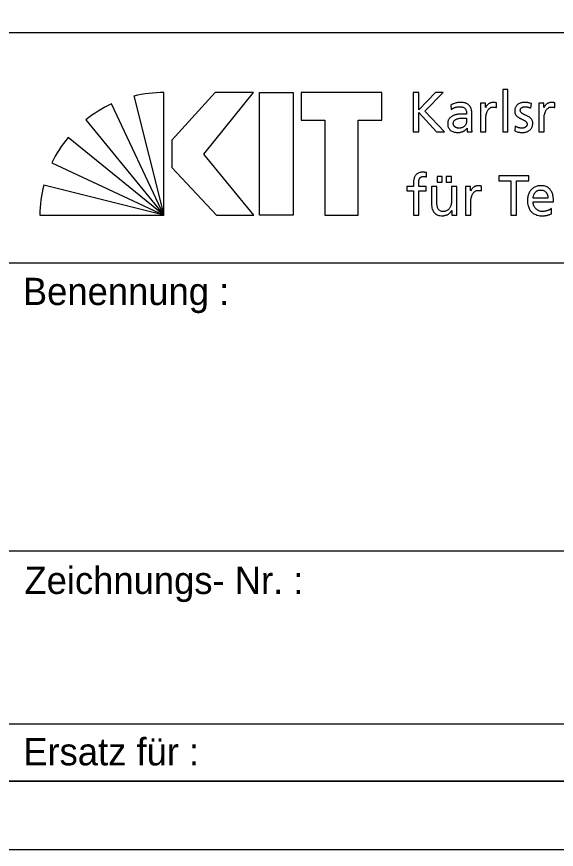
# Model space of a CAD drawing. Extents: x 0 to 1189, y 0 to 841.
# Drawn here: x 1100.7 to 1140.3, y 0 to 61.2 of the extents above; entities that cross this region are included whole.
import ezdxf

# ---------------------------------------------------------------- set-up
doc = ezdxf.new("R2010")
doc.units = 0
doc.layers.add('90_Plankopf', color=7, linetype='Continuous')

msp = doc.modelspace()

# ---------------------------------------------------------------- linework, layer by layer
at = {"layer": '90_Plankopf'}
for p, q in [((1006.12, 59.99), (1184, 59.99)), ((1006.12, 59.99), (1184, 59.99)), ((1109.275, 55.333), (1111.481, 46.586)), ((1111.481, 46.586), (1111.481, 55.584)), ((1129.81, 55.586), (1129.81, 52.706)), ((1111.481, 46.586), (1107.633, 54.752)), ((1132.579, 54.662), (1132.6, 54.332)), ((1135.926, 54.484), (1135.926, 54.831)), ((1138.457, 54.439), (1138.49, 54.778)), ((1140.211, 54.484), (1140.211, 54.831)), ((1134.118, 53.118), (1134.118, 53.989)), ((1105.744, 53.585), (1111.481, 46.586)), ((1133.73, 53.709), (1133.73, 53.523)), ((1129.81, 52.706), (1130.222, 52.706)), ((1131.506, 52.706), (1132.108, 52.706)), ((1137.297, 53.118), (1137.277, 52.772)), ((1111.481, 46.586), (1104.434, 52.286)), ((1103.24, 50.413), (1111.481, 46.586)), ((1130.773, 49.393), (1130.79, 49.706)), ((1111.481, 46.586), (1102.658, 48.788)), ((1134.827, 48.365), (1134.827, 48.712)), ((1139.706, 47.841), (1138.616, 47.841)), ((1138.616, 47.552), (1140.119, 47.552)), ((1102.364, 46.586), (1111.481, 46.586)), ((1139.958, 46.673), (1139.958, 47.061)), ((1100.001, 43.07), (1184, 43.07)), ((1100.001, 21.92), (1184, 21.92)), ((1100.001, 9.23), (1184, 9.23)), ((1184, 5), (1006.12, 5)), ((1017.8, 5), (1184, 5)), ((1017.8, 5), (1184, 5))]:
    msp.add_line(p, q, dxfattribs=at)
for points in [[(0, 0), (1189, 0), (1189, 841), (0, 841)], [(25, 5), (1184, 5), (1184, 836), (25, 836)], [(1118.066, 55.586), (1115.236, 55.586), (1112.073, 52.099), (1112.073, 50.092), (1115.338, 46.586), (1118.085, 46.586), (1114.422, 51.063)], [(1120.97, 55.586), (1120.97, 46.586), (1118.501, 46.586), (1118.501, 55.586)], [(1121.562, 55.586), (1121.562, 53.56), (1123.301, 53.56), (1123.301, 46.586), (1125.771, 46.586), (1125.771, 53.56), (1127.51, 53.56), (1127.51, 55.586)]]:
    msp.add_lwpolyline(points, close=True, dxfattribs=at)
for points in [[(1136.381, 52.706), (1136.768, 52.706), (1136.768, 55.801), (1136.381, 55.801), (1136.381, 52.706)], [(1132.108, 52.706), (1130.647, 54.224), (1132.001, 55.586), (1131.452, 55.586), (1130.222, 54.319), (1130.222, 55.586), (1129.81, 55.586)], [(1135.122, 54.484), (1135.113, 54.484), (1135.113, 54.81), (1134.75, 54.81), (1134.75, 52.706), (1135.138, 52.706), (1135.138, 53.663)], [(1139.407, 54.484), (1139.398, 54.484), (1139.398, 54.81), (1139.035, 54.81), (1139.035, 52.706), (1139.423, 52.706), (1139.423, 53.663)], [(1130.222, 52.706), (1130.222, 54.117), (1131.506, 52.706)], [(1133.763, 52.978), (1133.772, 52.978), (1133.772, 52.706), (1134.135, 52.706)], [(1131.554, 49.426), (1131.554, 49.013), (1131.942, 49.013), (1131.942, 49.426), (1131.554, 49.426)], [(1132.231, 49.426), (1132.231, 49.013), (1132.619, 49.013), (1132.619, 49.426), (1132.231, 49.426)], [(1136.99, 46.586), (1137.403, 46.586), (1137.403, 49.104), (1138.298, 49.104), (1138.298, 49.467), (1136.094, 49.467), (1136.094, 49.104), (1136.99, 49.104), (1136.99, 46.586)], [(1129.824, 48.885), (1129.824, 48.691), (1129.329, 48.691), (1129.329, 48.378), (1129.824, 48.378), (1129.824, 46.586), (1130.212, 46.586), (1130.212, 48.378), (1130.769, 48.378), (1130.769, 48.691), (1130.212, 48.691), (1130.212, 48.918)], [(1131.542, 47.602), (1131.542, 48.691), (1131.154, 48.691), (1131.154, 47.441)], [(1133.015, 46.586), (1133.015, 48.691), (1132.627, 48.691), (1132.627, 47.717)], [(1134.022, 48.365), (1134.014, 48.365), (1134.014, 48.691), (1133.651, 48.691), (1133.651, 46.586), (1134.039, 46.586), (1134.039, 47.544)], [(1132.631, 46.921), (1132.639, 46.921), (1132.639, 46.586), (1133.015, 46.586)]]:
    msp.add_lwpolyline(points, dxfattribs=at)
for centre, start, end in [((1111.449, 46.056), 89.80527, 103.18947), ((1111.662, 46.118), 115.01261, 128.3968), ((1111.816, 46.263), 140.78977, 154.17397), ((1111.891, 46.438), 165.72225, 179.10644)]:
    msp.add_arc(centre, 9.528, start, end, dxfattribs=at)
for points in [[(1134.118, 53.989), (1134.119, 54.18), (1134.091, 54.341), (1134.033, 54.47), (1133.975, 54.599), (1133.884, 54.696), (1133.759, 54.762), (1133.635, 54.827), (1133.472, 54.86), (1133.272, 54.86), (1133.138, 54.859), (1133.014, 54.841), (1132.898, 54.804), (1132.782, 54.768), (1132.676, 54.721), (1132.579, 54.662)], [(1132.6, 54.332), (1132.653, 54.376), (1132.713, 54.414), (1132.779, 54.446), (1132.846, 54.478), (1132.916, 54.503), (1132.99, 54.52), (1133.063, 54.538), (1133.137, 54.546), (1133.21, 54.546), (1133.339, 54.546), (1133.441, 54.526), (1133.518, 54.485), (1133.594, 54.444), (1133.649, 54.383), (1133.682, 54.302), (1133.715, 54.219), (1133.731, 54.118), (1133.73, 53.997)], [(1135.926, 54.831), (1135.899, 54.837), (1135.873, 54.841), (1135.849, 54.846), (1135.824, 54.85), (1135.798, 54.854), (1135.769, 54.856), (1135.741, 54.859), (1135.708, 54.86), (1135.67, 54.86), (1135.595, 54.859), (1135.523, 54.843), (1135.452, 54.811), (1135.382, 54.779), (1135.318, 54.736), (1135.261, 54.679), (1135.203, 54.623), (1135.157, 54.558), (1135.122, 54.484)], [(1135.138, 53.663), (1135.139, 53.84), (1135.163, 53.993), (1135.21, 54.121), (1135.257, 54.249), (1135.323, 54.348), (1135.409, 54.416), (1135.494, 54.486), (1135.595, 54.521), (1135.712, 54.521), (1135.746, 54.522), (1135.78, 54.519), (1135.818, 54.514), (1135.855, 54.509), (1135.891, 54.499), (1135.926, 54.484)], [(1138.49, 54.778), (1138.414, 54.801), (1138.337, 54.82), (1138.259, 54.836), (1138.181, 54.851), (1138.097, 54.859), (1138.007, 54.86), (1137.903, 54.86), (1137.805, 54.847), (1137.716, 54.82), (1137.625, 54.794), (1137.547, 54.753), (1137.48, 54.7), (1137.412, 54.647), (1137.359, 54.579), (1137.322, 54.498), (1137.284, 54.417), (1137.265, 54.321), (1137.264, 54.212), (1137.265, 54.128), (1137.282, 54.056), (1137.315, 53.994), (1137.347, 53.933), (1137.391, 53.88), (1137.445, 53.834), (1137.5, 53.79), (1137.559, 53.75), (1137.623, 53.715), (1137.688, 53.68), (1137.753, 53.647), (1137.817, 53.617), (1137.882, 53.586), (1137.942, 53.555), (1137.995, 53.522), (1138.05, 53.49), (1138.093, 53.454), (1138.126, 53.413), (1138.158, 53.373), (1138.176, 53.325), (1138.176, 53.271), (1138.176, 53.215), (1138.163, 53.167), (1138.139, 53.128), (1138.116, 53.09), (1138.084, 53.059), (1138.045, 53.035), (1138.006, 53.012), (1137.963, 52.995), (1137.917, 52.985), (1137.871, 52.975), (1137.825, 52.97), (1137.78, 52.97), (1137.742, 52.97), (1137.695, 52.975), (1137.639, 52.986), (1137.584, 52.997), (1137.526, 53.014), (1137.466, 53.036), (1137.405, 53.058), (1137.35, 53.085), (1137.297, 53.118)], [(1137.277, 52.772), (1137.366, 52.726), (1137.46, 52.694), (1137.558, 52.678), (1137.656, 52.662), (1137.755, 52.655), (1137.854, 52.656), (1137.949, 52.656), (1138.04, 52.669), (1138.127, 52.695), (1138.215, 52.722), (1138.293, 52.762), (1138.363, 52.816), (1138.431, 52.869), (1138.487, 52.938), (1138.527, 53.02), (1138.568, 53.103), (1138.588, 53.2), (1138.589, 53.312), (1138.588, 53.408), (1138.571, 53.489), (1138.539, 53.556), (1138.506, 53.622), (1138.462, 53.679), (1138.408, 53.726), (1138.354, 53.772), (1138.295, 53.811), (1138.23, 53.845), (1138.165, 53.878), (1138.101, 53.909), (1138.036, 53.937), (1137.971, 53.966), (1137.912, 53.995), (1137.858, 54.026), (1137.804, 54.058), (1137.76, 54.095), (1137.727, 54.136), (1137.695, 54.179), (1137.678, 54.23), (1137.677, 54.291), (1137.678, 54.348), (1137.696, 54.396), (1137.729, 54.434), (1137.763, 54.472), (1137.808, 54.5), (1137.864, 54.519), (1137.92, 54.538), (1137.982, 54.546), (1138.048, 54.546), (1138.072, 54.546), (1138.102, 54.543), (1138.139, 54.538), (1138.175, 54.531), (1138.213, 54.523), (1138.254, 54.513), (1138.295, 54.503), (1138.333, 54.491), (1138.369, 54.478), (1138.405, 54.466), (1138.434, 54.453), (1138.457, 54.439)], [(1140.211, 54.831), (1140.184, 54.837), (1140.158, 54.841), (1140.134, 54.846), (1140.11, 54.85), (1140.083, 54.854), (1140.054, 54.856), (1140.026, 54.859), (1139.993, 54.86), (1139.955, 54.86), (1139.88, 54.859), (1139.808, 54.843), (1139.737, 54.811), (1139.667, 54.779), (1139.603, 54.736), (1139.546, 54.679), (1139.488, 54.623), (1139.442, 54.558), (1139.407, 54.484)], [(1139.423, 53.663), (1139.424, 53.84), (1139.448, 53.993), (1139.495, 54.121), (1139.542, 54.249), (1139.608, 54.348), (1139.694, 54.416), (1139.779, 54.486), (1139.88, 54.521), (1139.997, 54.521), (1140.03, 54.522), (1140.065, 54.519), (1140.103, 54.514), (1140.14, 54.509), (1140.175, 54.499), (1140.211, 54.484)], [(1133.73, 53.997), (1133.68, 54), (1133.633, 54.002), (1133.589, 54.003), (1133.546, 54.004), (1133.502, 54.005), (1133.459, 54.006), (1133.415, 54.006), (1133.368, 54.006), (1133.318, 54.006), (1133.237, 54.006), (1133.151, 53.999), (1133.063, 53.984), (1132.973, 53.97), (1132.886, 53.947), (1132.801, 53.914), (1132.715, 53.881), (1132.638, 53.838), (1132.569, 53.785), (1132.499, 53.731), (1132.444, 53.665), (1132.403, 53.588), (1132.362, 53.509), (1132.341, 53.418), (1132.34, 53.312), (1132.341, 53.16), (1132.374, 53.035), (1132.439, 52.939), (1132.504, 52.842), (1132.594, 52.77), (1132.71, 52.724), (1132.825, 52.679), (1132.959, 52.656), (1133.111, 52.656), (1133.2, 52.657), (1133.28, 52.668), (1133.35, 52.689), (1133.421, 52.709), (1133.483, 52.736), (1133.536, 52.769), (1133.59, 52.802), (1133.635, 52.837), (1133.673, 52.874), (1133.71, 52.911), (1133.741, 52.945), (1133.763, 52.978)], [(1133.73, 53.523), (1133.73, 53.418), (1133.708, 53.323), (1133.664, 53.24), (1133.62, 53.157), (1133.554, 53.092), (1133.467, 53.043), (1133.38, 52.995), (1133.272, 52.97), (1133.144, 52.97), (1133.1, 52.97), (1133.054, 52.978), (1133.008, 52.992), (1132.963, 53.007), (1132.92, 53.028), (1132.882, 53.057), (1132.843, 53.087), (1132.812, 53.123), (1132.789, 53.165), (1132.765, 53.207), (1132.753, 53.257), (1132.752, 53.312), (1132.754, 53.386), (1132.772, 53.448), (1132.808, 53.497), (1132.844, 53.546), (1132.891, 53.586), (1132.949, 53.615), (1133.007, 53.645), (1133.069, 53.667), (1133.135, 53.682), (1133.201, 53.696), (1133.265, 53.706), (1133.326, 53.711), (1133.387, 53.715), (1133.439, 53.717), (1133.483, 53.717), (1133.524, 53.717), (1133.565, 53.715), (1133.607, 53.713), (1133.648, 53.711), (1133.689, 53.709), (1133.73, 53.709)], [(1134.135, 52.706), (1134.132, 52.726), (1134.129, 52.753), (1134.126, 52.787), (1134.125, 52.821), (1134.122, 52.865), (1134.121, 52.919), (1134.119, 52.973), (1134.118, 53.039), (1134.118, 53.118)], [(1130.79, 49.706), (1130.751, 49.712), (1130.71, 49.719), (1130.668, 49.723), (1130.625, 49.728), (1130.579, 49.731), (1130.53, 49.731), (1130.388, 49.73), (1130.27, 49.71), (1130.178, 49.671), (1130.086, 49.631), (1130.014, 49.574), (1129.962, 49.5), (1129.91, 49.426), (1129.875, 49.337), (1129.854, 49.233), (1129.833, 49.129), (1129.824, 49.014), (1129.824, 48.885)], [(1130.212, 48.918), (1130.212, 48.99), (1130.216, 49.056), (1130.224, 49.116), (1130.232, 49.177), (1130.249, 49.23), (1130.275, 49.275), (1130.3, 49.32), (1130.338, 49.355), (1130.388, 49.379), (1130.439, 49.404), (1130.505, 49.417), (1130.588, 49.417), (1130.621, 49.417), (1130.655, 49.415), (1130.688, 49.411), (1130.722, 49.407), (1130.75, 49.401), (1130.773, 49.393)], [(1134.827, 48.712), (1134.8, 48.717), (1134.774, 48.722), (1134.75, 48.727), (1134.725, 48.731), (1134.698, 48.734), (1134.67, 48.737), (1134.642, 48.739), (1134.609, 48.74), (1134.571, 48.74), (1134.496, 48.74), (1134.423, 48.724), (1134.352, 48.692), (1134.282, 48.66), (1134.218, 48.616), (1134.161, 48.56), (1134.104, 48.503), (1134.057, 48.439), (1134.022, 48.365)], [(1134.039, 47.544), (1134.039, 47.721), (1134.064, 47.873), (1134.11, 48.001), (1134.158, 48.129), (1134.224, 48.228), (1134.31, 48.297), (1134.395, 48.367), (1134.496, 48.401), (1134.612, 48.402), (1134.646, 48.403), (1134.681, 48.4), (1134.718, 48.395), (1134.756, 48.389), (1134.791, 48.379), (1134.827, 48.365)], [(1140.119, 47.552), (1140.119, 47.722), (1140.103, 47.88), (1140.072, 48.023), (1140.041, 48.168), (1139.989, 48.293), (1139.918, 48.4), (1139.846, 48.507), (1139.751, 48.591), (1139.631, 48.65), (1139.512, 48.709), (1139.365, 48.74), (1139.19, 48.74), (1139.041, 48.74), (1138.906, 48.714), (1138.785, 48.662), (1138.665, 48.61), (1138.561, 48.537), (1138.474, 48.442), (1138.387, 48.347), (1138.321, 48.235), (1138.275, 48.105), (1138.228, 47.976), (1138.205, 47.833), (1138.204, 47.676), (1138.204, 47.504), (1138.225, 47.348), (1138.269, 47.209), (1138.312, 47.069), (1138.379, 46.95), (1138.469, 46.85), (1138.558, 46.749), (1138.671, 46.672), (1138.808, 46.619), (1138.945, 46.564), (1139.107, 46.538), (1139.293, 46.537), (1139.408, 46.538), (1139.506, 46.545), (1139.587, 46.56), (1139.667, 46.575), (1139.737, 46.593), (1139.797, 46.614), (1139.855, 46.634), (1139.909, 46.654), (1139.958, 46.673)], [(1138.616, 47.841), (1138.623, 47.91), (1138.639, 47.978), (1138.664, 48.047), (1138.688, 48.116), (1138.722, 48.179), (1138.768, 48.236), (1138.812, 48.294), (1138.869, 48.339), (1138.937, 48.374), (1139.006, 48.408), (1139.087, 48.426), (1139.182, 48.427), (1139.266, 48.426), (1139.34, 48.411), (1139.404, 48.381), (1139.47, 48.35), (1139.524, 48.309), (1139.569, 48.255), (1139.614, 48.201), (1139.648, 48.139), (1139.671, 48.069), (1139.694, 47.998), (1139.706, 47.922), (1139.706, 47.841)], [(1132.627, 47.717), (1132.627, 47.589), (1132.615, 47.471), (1132.589, 47.365), (1132.564, 47.26), (1132.525, 47.169), (1132.473, 47.092), (1132.421, 47.015), (1132.354, 46.956), (1132.273, 46.914), (1132.193, 46.872), (1132.097, 46.851), (1131.987, 46.85), (1131.875, 46.857), (1131.786, 46.889), (1131.721, 46.945), (1131.656, 47.002), (1131.61, 47.084), (1131.582, 47.193), (1131.554, 47.302), (1131.541, 47.438), (1131.542, 47.602)], [(1131.154, 47.441), (1131.154, 47.251), (1131.181, 47.09), (1131.237, 46.955), (1131.293, 46.82), (1131.379, 46.717), (1131.496, 46.645), (1131.612, 46.574), (1131.761, 46.538), (1131.942, 46.537), (1132.04, 46.538), (1132.135, 46.553), (1132.225, 46.583), (1132.315, 46.614), (1132.396, 46.658), (1132.466, 46.715), (1132.537, 46.772), (1132.592, 46.841), (1132.631, 46.921)], [(1139.958, 47.061), (1139.933, 47.041), (1139.899, 47.019), (1139.852, 46.995), (1139.806, 46.971), (1139.754, 46.948), (1139.694, 46.926), (1139.634, 46.904), (1139.572, 46.886), (1139.506, 46.872), (1139.44, 46.858), (1139.374, 46.851), (1139.309, 46.85), (1139.217, 46.851), (1139.13, 46.868), (1139.046, 46.902), (1138.964, 46.935), (1138.889, 46.983), (1138.825, 47.045), (1138.761, 47.107), (1138.71, 47.181), (1138.673, 47.267), (1138.636, 47.353), (1138.617, 47.448), (1138.616, 47.552)]]:
    msp.add_open_spline(points, degree=3, dxfattribs=at)

# ---------------------------------------------------------------- texts
for s, p in [('Benennung :', (1101.113, 39.979)), ('Zeichnungs- Nr. :', (1101.227, 18.758)), ('Ersatz für :', (1101.139, 6.169))]:
    msp.add_text(s, height=2, dxfattribs=at).set_placement(p)

doc.saveas('drawing.dxf')
